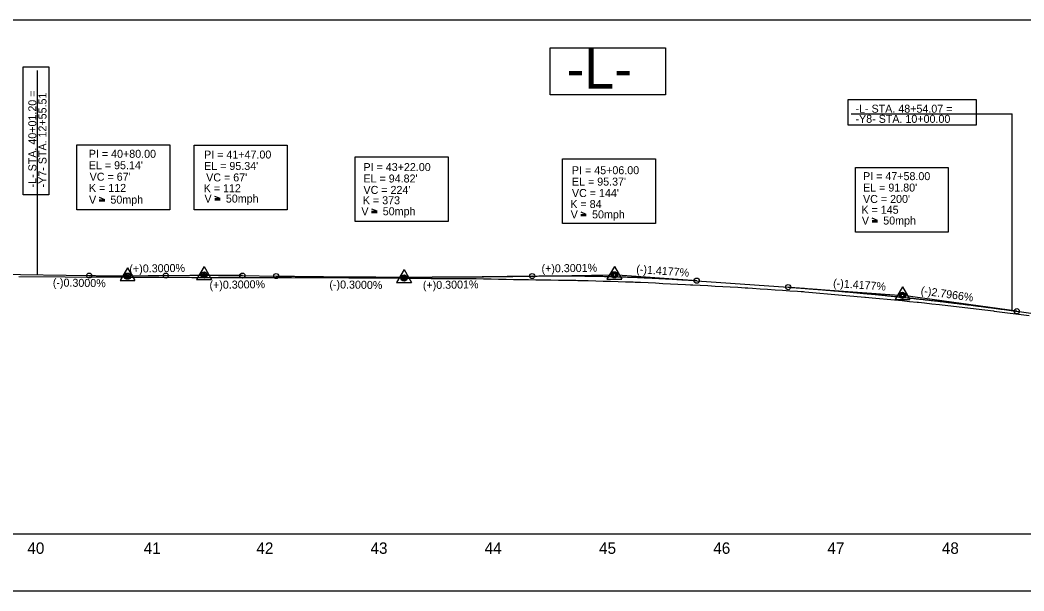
# Model space of a CAD drawing. Extents: x 2366464 to 2375718, y 801842 to 804354.
# Drawn here: x 2370304 to 2371182, y 803804 to 804304 of the extents above; entities that cross this region are included whole.
import ezdxf

# ---------------------------------------------------------------- set-up
doc = ezdxf.new("R2010")
doc.units = 0
for name, color, linetype in [('Exist Profile Cell', 7, 'Continuous'), ('Exist Vertical Profile Ground Line', 7, 'Continuous'), ('Exist Vertical Profile Horizontal Axis Label Major', 7, 'Continuous'), ('Prop Grid Mask', 7, 'Continuous'), ('Prop PFL VPI Symbol CELL', 7, 'Continuous'), ('Prop Vertical Profile Curve Label', 7, 'Continuous'), ('Prop Vertical Profile Grade', 7, 'Continuous'), ('Prop Vertical Profile Grade Label', 7, 'Continuous'), ('Prop VPI Label', 7, 'Continuous'), ('Scratch_Level_5', 7, 'Continuous'), ('Sheet Layout Profile Border Port 1', 7, 'Continuous')]:
    doc.layers.add(name, color=color, linetype=linetype)

# ---------------------------------------------------------------- blocks, each defined once
blk = doc.blocks.new('Profile VPI Symbol')
at = {"layer": 'Prop PFL VPI Symbol CELL'}
for p, q in [((-0.001, 0.147), (-0.13, -0.077)), ((-0.001, 0.147), (0.129, -0.077)), ((-0.13, -0.077), (0.129, -0.077))]:
    blk.add_line(p, q, dxfattribs=at)
for radius in [0.035, 0.024]:
    blk.add_circle((-0.001, -0.003), radius, dxfattribs=at)

msp = doc.modelspace()

# ---------------------------------------------------------------- linework, layer by layer
at = {"layer": 'Exist Profile Cell'}
msp.add_line((2367317.97, 803853.98), (2374481.84, 803853.98), dxfattribs=at)
at = {"layer": 'Exist Vertical Profile Ground Line'}
for points in [[(2370302.85, 804079.41), (2370343.43, 804079.08), (2370397.5, 804078.81), (2370398.82, 804078.81), (2370454.15, 804078.44)], [(2370454.15, 804078.44), (2370455.5, 804078.43), (2370511.13, 804078.44), (2370511.49, 804078.44), (2370541.24, 804078.51), (2370541.58, 804078.51), (2370591.56, 804078.28), (2370641.39, 804077.79), (2370643.41, 804077.78), (2370663.8, 804077.72), (2370670.34, 804077.7), (2370676.88, 804077.68), (2370683.41, 804077.67), (2370689.95, 804077.65), (2370691.07, 804077.65), (2370693.44, 804077.66), (2370696.49, 804077.61), (2370703.03, 804077.49), (2370709.56, 804077.37), (2370716.1, 804077.25), (2370722.64, 804077.13), (2370729.17, 804077.01), (2370735.71, 804076.89), (2370740.87, 804076.79), (2370742.25, 804076.77), (2370748.78, 804076.68), (2370755.32, 804076.58), (2370761.86, 804076.48), (2370768.4, 804076.38), (2370774.93, 804076.28), (2370781.47, 804076.18), (2370788.24, 804076.08), (2370790.09, 804076.04), (2370791.94, 804076), (2370794.54, 804075.93), (2370801.08, 804075.74), (2370807.62, 804075.55), (2370814.15, 804075.36), (2370820.69, 804075.17), (2370827.23, 804074.98), (2370833.77, 804074.79), (2370840.3, 804074.6), (2370841.99, 804074.55), (2370843.29, 804074.51), (2370846.84, 804074.34), (2370853.38, 804074.03), (2370859.91, 804073.71), (2370866.45, 804073.39), (2370872.99, 804073.07), (2370879.53, 804072.75), (2370886.06, 804072.43), (2370890.45, 804072.21), (2370891.4, 804072.16), (2370892.6, 804072.09), (2370899.14, 804071.74), (2370905.67, 804071.38), (2370912.21, 804071.02), (2370918.75, 804070.66), (2370925.28, 804070.3), (2370931.82, 804069.93), (2370938.36, 804069.57), (2370939.74, 804069.49), (2370940.64, 804069.44), (2370944.9, 804069.15), (2370951.43, 804068.72), (2370957.97, 804068.28), (2370964.51, 804067.84), (2370971.04, 804067.4), (2370977.58, 804066.96), (2370984.12, 804066.52), (2370987.48, 804066.29), (2370989.3, 804066.17), (2370990.65, 804066.05), (2370993.99, 804065.76), (2370997.19, 804065.48), (2371003.73, 804064.9), (2371010.27, 804064.33), (2371016.8, 804063.75), (2371023.34, 804063.17), (2371029.88, 804062.59), (2371033.45, 804062.28), (2371036.41, 804062.01), (2371039.76, 804061.71), (2371042.95, 804061.41), (2371043.79, 804061.33), (2371049.49, 804060.78), (2371056.03, 804060.15), (2371062.56, 804059.51), (2371069.1, 804058.88), (2371075.64, 804058.25), (2371082.17, 804057.62), (2371088.71, 804056.98), (2371089.56, 804056.9), (2371089.97, 804056.85), (2371095.25, 804056.24), (2371101.78, 804055.49), (2371108.32, 804054.73), (2371140.46, 804051.01), (2371155.52, 804049.22), (2371156.11, 804049.14), (2371186.8, 804045.14)]]:
    msp.add_lwpolyline(points, dxfattribs=at)
at = {"layer": 'Prop Grid Mask'}
for points in [[(2370767.82, 804279.8), (2370868.54, 804279.8), (2370868.54, 804238.5), (2370767.82, 804238.5)], [(2370306.68, 804150.92), (2370306.68, 804263.04), (2370329.22, 804263.04), (2370329.22, 804150.92)], [(2371028.38, 804234.38), (2371140.5, 804234.38), (2371140.5, 804211.84), (2371028.38, 804211.84)], [(2370353.73, 804194.57), (2370435.05, 804194.57), (2370435.05, 804137.86), (2370353.73, 804137.86)], [(2370456.26, 804194.45), (2370537.58, 804194.45), (2370537.58, 804137.74), (2370456.26, 804137.74)], [(2370597.23, 804184.23), (2370678.55, 804184.23), (2370678.55, 804127.52), (2370597.23, 804127.52)], [(2370778.58, 804182.57), (2370859.9, 804182.57), (2370859.9, 804125.86), (2370778.58, 804125.86)], [(2371034.76, 804174.82), (2371116.08, 804174.82), (2371116.08, 804118.11), (2371034.76, 804118.11)]]:
    msp.add_lwpolyline(points, close=True, dxfattribs=at)
at = {"layer": 'Prop Vertical Profile Curve Label'}
for p, q in [((2370373.28, 804146.64), (2370378.01, 804146.64)), ((2370373.28, 804145.61), (2370378.01, 804145.61)), ((2370378.01, 804146.64), (2370373.37, 804148.64)), ((2370474.29, 804147.58), (2370479.01, 804147.58)), ((2370474.29, 804146.55), (2370479.01, 804146.55)), ((2370479.01, 804147.58), (2370474.38, 804149.58)), ((2370611.54, 804136.46), (2370616.27, 804136.46)), ((2370611.54, 804135.42), (2370616.27, 804135.42)), ((2370616.27, 804136.46), (2370611.64, 804138.46)), ((2370794.67, 804133.74), (2370799.4, 804133.74)), ((2370799.4, 804133.74), (2370794.77, 804135.73)), ((2370794.67, 804132.7), (2370799.4, 804132.7)), ((2371049.43, 804128.34), (2371054.16, 804128.34)), ((2371049.43, 804127.3), (2371054.16, 804127.3)), ((2371054.16, 804128.34), (2371049.52, 804130.34))]:
    msp.add_line(p, q, dxfattribs=at)
for centre in [(2370364.47, 804080.19), (2370364.47, 804080.19), (2370431.47, 804080.19), (2370431.47, 804080.19), (2370431.47, 804080.19), (2370431.47, 804080.19), (2370498.47, 804080.19), (2370498.47, 804080.19), (2370527.97, 804079.75), (2370751.97, 804079.75), (2370751.97, 804079.75), (2370895.97, 804075.73), (2370975.97, 804070.06), (2371175.97, 804048.98)]:
    msp.add_circle(centre, 2.25, dxfattribs=at)
at = {"layer": 'Prop Vertical Profile Grade'}
for p, q in [((2370262.97, 804081.72), (2370364.47, 804080.19)), ((2370498.47, 804080.19), (2370527.97, 804079.75)), ((2370895.97, 804075.73), (2370975.97, 804070.06)), ((2371175.97, 804048.98), (2371277.47, 804034.79))]:
    msp.add_line(p, q, dxfattribs=at)
for points in [[(2370364.47, 804080.19), (2370365.81, 804080.17), (2370367.15, 804080.15), (2370368.49, 804080.14), (2370369.83, 804080.12), (2370371.17, 804080.1), (2370372.51, 804080.09), (2370373.85, 804080.07), (2370375.19, 804080.06), (2370376.53, 804080.04), (2370377.87, 804080.03), (2370379.21, 804080.02), (2370380.55, 804080.01), (2370381.89, 804080), (2370383.23, 804079.99), (2370384.57, 804079.98), (2370385.91, 804079.97), (2370387.25, 804079.97), (2370388.59, 804079.96), (2370389.93, 804079.96), (2370391.27, 804079.95), (2370392.61, 804079.95), (2370393.95, 804079.95), (2370395.29, 804079.94), (2370396.63, 804079.94), (2370397.97, 804079.94), (2370399.31, 804079.94), (2370400.65, 804079.94), (2370401.99, 804079.95), (2370403.33, 804079.95), (2370404.67, 804079.95), (2370406.01, 804079.96), (2370407.35, 804079.96), (2370408.69, 804079.97), (2370410.03, 804079.97), (2370411.37, 804079.98), (2370412.71, 804079.99), (2370414.05, 804080), (2370415.39, 804080.01), (2370416.73, 804080.02), (2370418.07, 804080.03), (2370419.41, 804080.04), (2370420.75, 804080.06), (2370422.09, 804080.07), (2370423.43, 804080.09), (2370424.77, 804080.1), (2370426.11, 804080.12), (2370427.45, 804080.14), (2370428.79, 804080.15), (2370430.13, 804080.17), (2370431.47, 804080.19)], [(2370431.47, 804080.19), (2370432.81, 804080.21), (2370434.15, 804080.23), (2370435.49, 804080.25), (2370436.83, 804080.27), (2370438.17, 804080.28), (2370439.51, 804080.3), (2370440.85, 804080.31), (2370442.19, 804080.33), (2370443.53, 804080.34), (2370444.87, 804080.35), (2370446.21, 804080.37), (2370447.55, 804080.38), (2370448.89, 804080.39), (2370450.23, 804080.4), (2370451.57, 804080.4), (2370452.91, 804080.41), (2370454.25, 804080.42), (2370455.59, 804080.42), (2370456.93, 804080.43), (2370458.27, 804080.43), (2370459.61, 804080.44), (2370460.95, 804080.44), (2370462.29, 804080.44), (2370463.63, 804080.44), (2370464.97, 804080.44), (2370466.31, 804080.44), (2370467.65, 804080.44), (2370468.99, 804080.44), (2370470.33, 804080.44), (2370471.67, 804080.43), (2370473.01, 804080.43), (2370474.35, 804080.42), (2370475.69, 804080.42), (2370477.03, 804080.41), (2370478.37, 804080.4), (2370479.71, 804080.4), (2370481.05, 804080.39), (2370482.39, 804080.38), (2370483.73, 804080.37), (2370485.07, 804080.35), (2370486.41, 804080.34), (2370487.75, 804080.33), (2370489.09, 804080.31), (2370490.43, 804080.3), (2370491.77, 804080.28), (2370493.11, 804080.27), (2370494.45, 804080.25), (2370495.79, 804080.23), (2370497.13, 804080.21), (2370498.47, 804080.19)], [(2370527.97, 804079.75), (2370532.45, 804079.68), (2370536.93, 804079.62), (2370541.41, 804079.56), (2370545.89, 804079.5), (2370550.37, 804079.45), (2370554.85, 804079.4), (2370559.33, 804079.35), (2370563.81, 804079.3), (2370568.29, 804079.25), (2370572.77, 804079.21), (2370577.25, 804079.17), (2370581.73, 804079.14), (2370586.21, 804079.1), (2370590.69, 804079.07), (2370595.17, 804079.04), (2370599.65, 804079.02), (2370604.13, 804079), (2370608.61, 804078.98), (2370613.09, 804078.96), (2370617.57, 804078.94), (2370622.05, 804078.93), (2370626.53, 804078.92), (2370631.01, 804078.92), (2370635.49, 804078.91), (2370639.97, 804078.91), (2370644.45, 804078.91), (2370648.93, 804078.92), (2370653.41, 804078.92), (2370657.89, 804078.93), (2370662.37, 804078.94), (2370666.85, 804078.96), (2370671.33, 804078.98), (2370675.81, 804079), (2370680.29, 804079.02), (2370684.77, 804079.04), (2370689.25, 804079.07), (2370693.73, 804079.1), (2370698.21, 804079.14), (2370702.69, 804079.17), (2370707.17, 804079.21), (2370711.65, 804079.25), (2370716.13, 804079.3), (2370720.61, 804079.35), (2370725.09, 804079.4), (2370729.57, 804079.45), (2370734.05, 804079.5), (2370738.53, 804079.56), (2370743.01, 804079.62), (2370747.49, 804079.68), (2370751.97, 804079.75)], [(2370751.97, 804079.75), (2370754.85, 804079.79), (2370757.73, 804079.83), (2370760.61, 804079.86), (2370763.49, 804079.88), (2370766.37, 804079.9), (2370769.25, 804079.92), (2370772.13, 804079.93), (2370775.01, 804079.94), (2370777.89, 804079.94), (2370780.77, 804079.93), (2370783.65, 804079.93), (2370786.53, 804079.91), (2370789.41, 804079.89), (2370792.29, 804079.87), (2370795.17, 804079.84), (2370798.05, 804079.81), (2370800.93, 804079.77), (2370803.81, 804079.73), (2370806.69, 804079.68), (2370809.57, 804079.62), (2370812.45, 804079.57), (2370815.33, 804079.5), (2370818.21, 804079.44), (2370821.09, 804079.36), (2370823.97, 804079.28), (2370826.85, 804079.2), (2370829.73, 804079.11), (2370832.61, 804079.02), (2370835.49, 804078.92), (2370838.37, 804078.82), (2370841.25, 804078.71), (2370844.13, 804078.6), (2370847.01, 804078.48), (2370849.89, 804078.36), (2370852.77, 804078.23), (2370855.65, 804078.1), (2370858.53, 804077.96), (2370861.41, 804077.82), (2370864.29, 804077.67), (2370867.17, 804077.52), (2370870.05, 804077.36), (2370872.93, 804077.2), (2370875.81, 804077.03), (2370878.69, 804076.86), (2370881.57, 804076.69), (2370884.45, 804076.5), (2370887.33, 804076.32), (2370890.21, 804076.13), (2370893.09, 804075.93), (2370895.97, 804075.73)], [(2370975.97, 804070.06), (2370979.97, 804069.77), (2370983.97, 804069.48), (2370987.97, 804069.18), (2370991.97, 804068.88), (2370995.97, 804068.57), (2370999.97, 804068.26), (2371003.97, 804067.94), (2371007.97, 804067.61), (2371011.97, 804067.28), (2371015.97, 804066.94), (2371019.97, 804066.6), (2371023.97, 804066.26), (2371027.97, 804065.9), (2371031.97, 804065.55), (2371035.97, 804065.18), (2371039.97, 804064.81), (2371043.97, 804064.44), (2371047.97, 804064.06), (2371051.97, 804063.67), (2371055.97, 804063.28), (2371059.97, 804062.89), (2371063.97, 804062.48), (2371067.97, 804062.08), (2371071.97, 804061.66), (2371075.97, 804061.24), (2371079.97, 804060.82), (2371083.97, 804060.39), (2371087.97, 804059.95), (2371091.97, 804059.51), (2371095.97, 804059.07), (2371099.97, 804058.62), (2371103.97, 804058.16), (2371107.97, 804057.7), (2371111.97, 804057.23), (2371115.97, 804056.75), (2371119.97, 804056.27), (2371123.97, 804055.79), (2371127.97, 804055.3), (2371131.97, 804054.8), (2371135.97, 804054.3), (2371139.97, 804053.79), (2371143.97, 804053.28), (2371147.97, 804052.76), (2371151.97, 804052.24), (2371155.97, 804051.71), (2371159.97, 804051.18), (2371163.97, 804050.64), (2371167.97, 804050.09), (2371171.97, 804049.54), (2371175.97, 804048.98)]]:
    msp.add_spline(points, degree=3, dxfattribs=at)
at = {"layer": 'Prop VPI Label'}
for p, q in [((2370319.17, 804080.87), (2370319.17, 804259.78)), ((2371031.14, 804221.93), (2371172.04, 804221.93)), ((2371172.04, 804049.53), (2371172.04, 804221.93)), ((2370364.47, 804080.19), (2370395.22, 804079.73)), ((2370431.47, 804080.19), (2370400.72, 804079.73)), ((2370431.47, 804080.19), (2370462.22, 804080.65)), ((2370498.47, 804080.19), (2370467.72, 804080.65)), ((2370751.97, 804079.75), (2370821.22, 804080.79)), ((2370895.97, 804075.73), (2370826.72, 804080.64)), ((2370527.97, 804079.75), (2370637.22, 804078.11)), ((2370751.97, 804079.75), (2370642.72, 804078.11)), ((2370975.97, 804070.06), (2371073.23, 804063.16)), ((2371175.97, 804048.98), (2371078.7, 804062.59))]:
    msp.add_line(p, q, dxfattribs=at)
for centre in [(2370397.97, 804079.69), (2370464.97, 804080.7), (2370639.97, 804078.07), (2370823.97, 804080.83), (2371075.97, 804062.97)]:
    msp.add_circle(centre, 2.75, dxfattribs=at)
at = {"layer": 'Scratch_Level_5'}
for p, q in [((2370517.97, 804079.68), (2370517.97, 804079.68)), ((2370617.97, 804079.23), (2370617.97, 804079.23)), ((2370717.97, 804079.38), (2370717.97, 804079.38)), ((2370917.97, 804074.23), (2370917.97, 804074.23)), ((2371017.97, 804066.28), (2371017.97, 804066.28)), ((2371167.97, 804050.08), (2371167.97, 804050.08))]:
    msp.add_line(p, q, dxfattribs=at)
at = {"layer": 'Sheet Layout Profile Border Port 1'}
msp.add_lwpolyline([(2370117.97, 803803.98), (2371517.97, 803803.98), (2371517.97, 804303.98), (2370117.97, 804303.98)], close=True, dxfattribs=at)

# ---------------------------------------------------------------- block references
at = {"layer": 'Prop Grid Mask', "xscale": 50, "yscale": 50}
for p in [(2370397.97, 804079.69), (2370464.97, 804080.7), (2370639.97, 804078.07), (2370823.97, 804080.83), (2371075.97, 804062.97)]:
    msp.add_blockref('Profile VPI Symbol', p, dxfattribs=at)

# ---------------------------------------------------------------- texts
at = {"layer": 'Exist Vertical Profile Horizontal Axis Label Major'}
for s, p in [('40', (2370310.36, 803836.48)), ('41', (2370412.2, 803836.48)), ('42', (2370510.75, 803836.48)), ('43', (2370610.58, 803836.48)), ('44', (2370710.43, 803836.48)), ('45', (2370810.52, 803836.48)), ('46', (2370910.46, 803836.48)), ('47', (2371010.32, 803836.48)), ('48', (2371110.44, 803836.48))]:
    msp.add_text(s, height=10, dxfattribs=at).set_placement(p)
at = {"layer": 'Prop Vertical Profile Curve Label'}
for s, p in [('-L- STA. 40+01.20 = ', (2370318.24, 804157.44)), ('-Y7- STA. 12+55.51', (2370327.11, 804157.44))]:
    msp.add_text(s, height=7, rotation=90, dxfattribs=at).set_placement(p)
for s, p in [('-L- STA. 48+54.07 = ', (2371034.9, 804222.82)), ('-Y8- STA. 10+00.00', (2371034.9, 804213.95)), ("VC = 67'", (2370364.87, 804163.26)), ("VC = 67'", (2370466.8, 804162.66)), ('K = 112', (2370364.25, 804153.47)), ('K = 112', (2370464.64, 804153.18)), ('50mph', (2370383.03, 804143.19)), ('V', (2370465.34, 804144.05)), ('50mph', (2370484.04, 804144.13)), ("VC = 224'", (2370604.43, 804151.72)), ("VC = 144'", (2370786.82, 804148.98)), ("VC = 200'", (2371041.51, 804143.77)), ('V', (2370364.33, 804143.11)), ('K = 373', (2370603.89, 804142.66)), ('K = 84', (2370785.41, 804139.32)), ('V', (2370602.6, 804132.92)), ('50mph', (2370621.3, 804133.01)), ('V', (2370785.73, 804130.2)), ('50mph', (2370804.42, 804130.29)), ('K = 145', (2371040.11, 804134.33)), ('V', (2371040.48, 804124.81)), ('50mph', (2371059.18, 804124.89))]:
    msp.add_text(s, height=7, dxfattribs=at).set_placement(p)
at = {"layer": 'Prop Vertical Profile Grade Label'}
for s, rotation, p in [('(+)0.3000%', 0.85934, (2370399.7, 804082.72)), ('(+)0.3001%', 0.85962, (2370760.24, 804082.87)), ('(-)1.4177%', 355.94542, (2370842.92, 804082.49)), ('(-)0.3000%', 359.14065, (2370332.59, 804070.67)), ('(+)0.3000%', 0.85934, (2370469.75, 804068.47)), ('(-)0.3000%', 359.14039, (2370574.59, 804069.05)), ('(+)0.3001%', 0.85962, (2370656.43, 804068.32)), ('(-)1.4177%', 355.94542, (2371015.12, 804070.29)), ('(-)2.7966%', 352.03992, (2371091.66, 804063.8))]:
    msp.add_text(s, height=7, rotation=rotation, dxfattribs=at).set_placement(p)
at = {"layer": 'Prop VPI Label'}
for s, height, p in [('-L-', 35, (2370782.12, 804243.99)), ('PI = 40+80.00', 7, (2370364.12, 804183.35)), ('PI = 41+47.00', 7, (2370465, 804182.69)), ("EL = 95.14'", 7, (2370364.12, 804173.35)), ("EL = 95.34'", 7, (2370465, 804172.69)), ('PI = 43+22.00', 7, (2370604.43, 804171.72)), ("EL = 94.82'", 7, (2370604.43, 804161.72)), ('PI = 45+06.00', 7, (2370786.82, 804168.98)), ('PI = 47+58.00', 7, (2371041.51, 804163.77)), ("EL = 95.37'", 7, (2370786.82, 804158.98)), ("EL = 91.80'", 7, (2371041.51, 804153.77))]:
    msp.add_text(s, height=height, dxfattribs=at).set_placement(p)

doc.saveas('drawing.dxf')
